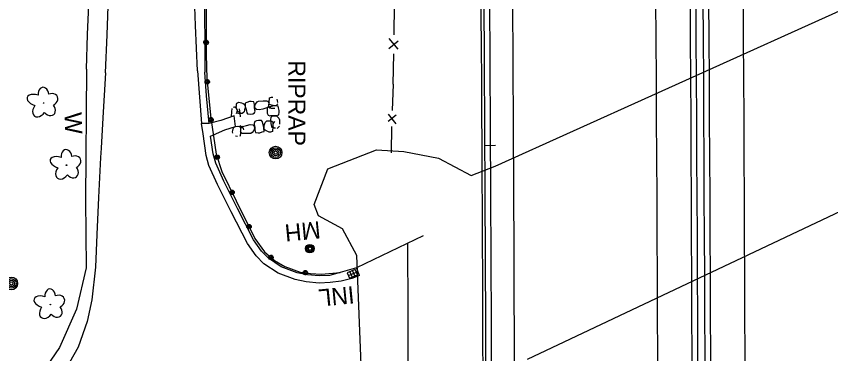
# Model space of a CAD drawing. Extents: x 588843 to 2552415, y 180129 to 269402.
# Drawn here: x 593781.7 to 594066, y 188272 to 188389.7 of the extents above; entities that cross this region are included whole.
import ezdxf

# ---------------------------------------------------------------- set-up
doc = ezdxf.new("R2010")
doc.units = 0
for name, color, linetype in [('Default', 7, 'Continuous'), ('E_AREA', 7, 'Continuous'), ('E_BMGRD_P', 7, 'Continuous'), ('E_DRN', 7, 'Continuous'), ('E_DRN_RipRap', 7, 'Continuous'), ('E_DRN_RipRap_Text', 7, 'Continuous'), ('E_DRN_Text', 7, 'Continuous'), ('E_FEN_P', 7, 'Continuous'), ('E_LAND_Vegetation', 7, 'Continuous'), ('E_MISCPROP', 7, 'Continuous'), ('E_RDWY', 7, 'Continuous'), ('E_RDWY_C_and_G', 7, 'Continuous'), ('E_RDWY_Gravel', 7, 'Continuous'), ('E_SGN', 7, 'Continuous'), ('E_UTL_MH', 7, 'Continuous'), ('E_UTL_MH_Text', 7, 'Continuous'), ('E_WAL', 7, 'Continuous'), ('E_WAL_Text', 7, 'Continuous'), ('P_RDWY_BarrierConc', 7, 'Continuous'), ('P_RDWY_C_and_G', 7, 'Continuous'), ('P_RDWY_C_and_GBack', 7, 'Continuous'), ('P_RDWY_C_and_GFace', 7, 'Continuous'), ('P_RDWY_PavtEdge', 7, 'Continuous')]:
    doc.layers.add(name, color=color, linetype=linetype)

# ---------------------------------------------------------------- blocks, each defined once
blk = doc.blocks.new('POLE')
at = {"layer": 'Default'}
for radius in [4.46, 3.35, 2.23, 1.12]:
    blk.add_circle((0, 0), radius, dxfattribs=at)
blk = doc.blocks.new('RIPRT')
at = {"layer": 'E_DRN_RipRap_Text'}
blk.add_text('RIPRAP', height=12, dxfattribs=at).set_placement((-0.14, -3.59))
blk = doc.blocks.new('INLO')
at = {"layer": 'E_DRN'}
for p, q in [((2, -4), (2, 0)), ((4, -4), (4, 0)), ((6, -2), (0, -2))]:
    blk.add_line(p, q, dxfattribs=at)
blk.add_lwpolyline([(0, -4), (6, -4), (6, 0), (0, 0), (0, -4)], close=True, dxfattribs=at)
blk = doc.blocks.new('INLT_37')
at = {"layer": 'E_DRN_Text'}
blk.add_text('INL', height=12, dxfattribs=at).set_placement((-11.03, -6))
blk = doc.blocks.new('MHO')
at = {"layer": 'Default'}
for centre, radius in [((0.08, -0.12), 3), ((0.08, -0.12), 2.43), ((0.07, -0.15), 1.94), ((0.02, -0.16), 1.21)]:
    blk.add_circle(centre, radius, dxfattribs=at)
blk = doc.blocks.new('MHT')
at = {"layer": 'E_UTL_MH_Text'}
blk.add_text('MH', height=12, dxfattribs=at).set_placement((-9.81, -6))
blk = doc.blocks.new('DTRE')
at = {"layer": 'Default'}
blk.add_circle((-0.18, 0), 0.183, dxfattribs=at)
for centre, major_axis, ratio in [((-1.87, 5.32), (1.36, -4.98), 0.782863), ((4.06, 2.74), (-5.27, -2.93), 0.691916), ((-5.87, 0.15), (4.93, -0.12), 0.832022), ((-2.49, -5.24), (1.8, 4.86), 0.716896), ((3.54, -3.71), (-5.01, 4.58), 0.560249)]:
    blk.add_ellipse(centre, major_axis=major_axis, ratio=ratio, start_param=1.570796, end_param=4.712389, dxfattribs=at)
blk = doc.blocks.new('W_26')
at = {"layer": 'E_WAL_Text'}
blk.add_text('W', height=12, dxfattribs=at).set_placement((-4.46, -6))

msp = doc.modelspace()

# ---------------------------------------------------------------- linework, layer by layer
at = {"layer": 'E_AREA'}
for points in [[(593902.79, 188250.54), (593900.56, 188306.25), (593895.49, 188315.57), (593887.11, 188320.1), (593885.68, 188323.97), (593890.4, 188336.47), (593907.43, 188343.11), (593916.95, 188342.51), (593929.09, 188340.24), (593940.49, 188334.14), (593948.81, 188337.39), (594085.58, 188399.16)], [(594080.03, 188326.7), (593960.02, 188269.93)]]:
    msp.add_lwpolyline(points, dxfattribs=at)
at = {"layer": 'E_BMGRD_P'}
for points in [[(593861.83, 188614.96), (593858.45, 188567.52), (593852.51, 188499.89), (593850.25, 188462.79), (593848.24, 188422.71), (593847.93, 188392.95), (593847.94, 188376.23), (593848.22, 188367.94)], [(593848.22, 188367.94), (593849.53, 188354.1), (593851.43, 188341.57), (593853.46, 188335.53), (593858.44, 188325.26), (593864.96, 188312.17), (593868.35, 188307.56), (593871.75, 188304.54), (593875.38, 188302.45), (593880.75, 188300.47), (593884.37, 188300), (593888.21, 188299.76), (593894.75, 188300.27)]]:
    msp.add_lwpolyline(points, dxfattribs=at)
for centre, radius in [((593851.79, 188340.51), 0.776), ((593851.79, 188340.51), 0.391), ((593856.99, 188328.26), 0.776), ((593856.99, 188328.26), 0.391), ((593862.9, 188316.32), 0.776), ((593862.9, 188316.32), 0.391)]:
    msp.add_circle(centre, radius, dxfattribs=at)
for centre, major_axis, ratio in [((593847.94, 188380.54), (0.259, 0.758), 0.999873), ((593847.94, 188380.54), (0.13, 0.382), 0.999873), ((593848.32, 188366.84), (0.774, 0.061), 0.998241), ((593848.32, 188366.84), (0.39, 0.031), 0.998241), ((593849.61, 188353.6), (0.767, 0.123), 0.996546), ((593849.61, 188353.6), (0.386, 0.062), 0.996546), ((593870.57, 188305.58), (-0.58, 0.516), 0.999998), ((593870.58, 188305.58), (-0.292, 0.26), 0.999998), ((593882.58, 188300.23), (-0.77, 0.1), 0.999994), ((593882.58, 188300.23), (-0.388, 0.05), 0.999994)]:
    msp.add_ellipse(centre, major_axis=major_axis, ratio=ratio, dxfattribs=at)
at = {"layer": 'E_DRN_RipRap'}
for p, q in [((593870.07, 188361.19), (593870.71, 188361.45)), ((593870.71, 188361.45), (593871.19, 188361.41)), ((593858.48, 188358.2), (593858.58, 188359.04)), ((593858.58, 188359.04), (593858.65, 188359.42)), ((593858.65, 188359.42), (593859.29, 188359.67)), ((593859.29, 188359.67), (593859.76, 188359.64)), ((593859.76, 188359.64), (593860.28, 188359.51)), ((593860.28, 188359.51), (593860.84, 188359.25)), ((593860.84, 188359.25), (593861.22, 188358.99)), ((593861.22, 188358.99), (593861.37, 188358.88)), ((593861.37, 188358.88), (593861.55, 188358.36)), ((593862.19, 188359.6), (593861.57, 188359.42)), ((593861.57, 188359.42), (593861.59, 188358.15)), ((593863.11, 188359.9), (593862.19, 188359.6)), ((593863.66, 188359.9), (593863.11, 188359.9)), ((593864.58, 188359.83), (593863.66, 188359.9)), ((593864.8, 188358.91), (593864.58, 188359.83)), ((593864.85, 188357.94), (593864.8, 188358.91)), ((593864.96, 188358.41), (593865.12, 188359.07)), ((593865.12, 188359.07), (593865.7, 188359.82)), ((593865.7, 188359.82), (593866.26, 188360.09)), ((593866.26, 188360.09), (593867.81, 188360.18)), ((593867.81, 188360.18), (593868.99, 188360.15)), ((593868.99, 188360.15), (593869.39, 188360.08)), ((593869.39, 188360.08), (593869.89, 188359.39)), ((593869.57, 188358.07), (593869.85, 188358.61)), ((593869.84, 188358.37), (593869.9, 188359.97)), ((593869.85, 188358.61), (593869.89, 188359.39)), ((593869.9, 188359.97), (593870, 188360.81)), ((593870, 188360.81), (593870.07, 188361.19)), ((593870.74, 188358.7), (593870.07, 188358.89)), ((593871.35, 188358.53), (593870.74, 188358.7)), ((593872.01, 188358.44), (593871.35, 188358.53)), ((593872.54, 188358.6), (593872.01, 188358.44)), ((593872.65, 188358.74), (593872.54, 188358.6)), ((593872.62, 188360.78), (593872.76, 188360.26)), ((593872.92, 188359.11), (593872.65, 188358.74)), ((593872.76, 188360.26), (593872.81, 188359.64)), ((593856.8, 188354.77), (593856.86, 188356.34)), ((593856.86, 188356.34), (593857, 188357.51)), ((593857.44, 188357.98), (593857.83, 188358.08)), ((593857.83, 188358.08), (593858.56, 188357.66)), ((593858.93, 188356.71), (593858.34, 188358.2)), ((593858.84, 188356.94), (593858.56, 188357.66)), ((593858.57, 188355.81), (593858.82, 188356.32)), ((593859.26, 188355.72), (593858.76, 188355.88)), ((593858.82, 188356.32), (593858.84, 188356.94)), ((593859.22, 188356.31), (593858.93, 188356.71)), ((593859.53, 188356.2), (593859.22, 188356.31)), ((593859.99, 188355.73), (593859.26, 188355.72)), ((593859.41, 188357.37), (593859.7, 188355.93)), ((593859.7, 188355.93), (593859.8, 188354.6)), ((593860.53, 188355.79), (593859.99, 188355.73)), ((593860.98, 188356.07), (593860.53, 188355.79)), ((593861.22, 188356.37), (593860.98, 188356.07)), ((593861.37, 188357.06), (593861.22, 188356.37)), ((593861.5, 188357.69), (593861.37, 188357.06)), ((593861.55, 188358.36), (593861.5, 188357.69)), ((593861.59, 188358.15), (593861.77, 188357.49)), ((593861.77, 188357.49), (593861.98, 188356.65)), ((593861.98, 188356.65), (593862.13, 188356.03)), ((593862.13, 188356.03), (593862.42, 188355.66)), ((593862.42, 188355.66), (593862.56, 188355.6)), ((593862.56, 188355.6), (593863.5, 188355.58)), ((593863.5, 188355.58), (593864.24, 188355.67)), ((593864.24, 188355.67), (593864.85, 188356.01)), ((593864.98, 188356.96), (593864.85, 188357.94)), ((593864.85, 188356.01), (593865.07, 188356.6)), ((593865.04, 188357.55), (593864.96, 188358.41)), ((593865.07, 188356.6), (593864.98, 188356.96)), ((593865.5, 188357.14), (593865.04, 188357.55)), ((593866.45, 188357.05), (593865.5, 188357.14)), ((593867.74, 188357.28), (593866.45, 188357.05)), ((593869.14, 188357.71), (593867.74, 188357.28)), ((593869.14, 188357.71), (593869.57, 188358.07)), ((593869.25, 188357.57), (593869.2, 188356.62)), ((593869.2, 188356.62), (593869.25, 188355.86)), ((593869.32, 188357.71), (593869.25, 188357.57)), ((593869.25, 188355.86), (593869.55, 188355.23)), ((593869.7, 188357.99), (593869.32, 188357.71)), ((593870.11, 188358.03), (593869.64, 188358.3)), ((593870.31, 188358.1), (593869.7, 188357.99)), ((593869.94, 188357.88), (593869.84, 188358.37)), ((593870.19, 188357.66), (593869.94, 188357.88)), ((593870.49, 188357.96), (593870.11, 188358.03)), ((593870.68, 188357.5), (593870.19, 188357.66)), ((593871.15, 188358.27), (593870.31, 188358.1)), ((593871.41, 188357.5), (593870.68, 188357.5)), ((593871.81, 188358.42), (593871.15, 188358.27)), ((593871.95, 188357.56), (593871.41, 188357.5)), ((593873.05, 188358.36), (593871.81, 188358.42)), ((593873.2, 188357.72), (593873.05, 188358.36)), ((593873.46, 188356.77), (593873.2, 188357.72)), ((593873.33, 188355.29), (593873.44, 188356.22)), ((593873.44, 188356.22), (593873.46, 188356.77)), ((593864.88, 188352.92), (593864.66, 188352.33)), ((593865.47, 188353.26), (593864.88, 188352.92)), ((593866.21, 188353.35), (593865.47, 188353.26)), ((593867.14, 188353.34), (593866.21, 188353.35)), ((593867.28, 188353.28), (593867.14, 188353.34)), ((593867.58, 188352.91), (593867.28, 188353.28)), ((593867.73, 188352.3), (593867.58, 188352.91)), ((593868.49, 188352.57), (593868.72, 188352.88)), ((593868.72, 188352.88), (593869.17, 188353.16)), ((593869.17, 188353.16), (593869.7, 188353.22)), ((593869.55, 188355.23), (593870.13, 188354.98)), ((593869.7, 188353.22), (593870.42, 188353.23)), ((593870.13, 188354.98), (593870.48, 188355.04)), ((593870.42, 188353.23), (593870.92, 188353.07)), ((593870.48, 188355.04), (593871.46, 188355.12)), ((593870.51, 188353.55), (593870.64, 188354.51)), ((593870.68, 188352.22), (593870.51, 188353.55)), ((593870.64, 188354.51), (593871.06, 188354.95)), ((593870.92, 188353.07), (593871.16, 188352.85)), ((593871.06, 188354.95), (593871.91, 188354.98)), ((593871.16, 188352.85), (593871.27, 188352.36)), ((593871.46, 188355.12), (593872.42, 188355.11)), ((593871.96, 188353.03), (593871.53, 188352.67)), ((593871.91, 188354.98), (593872.56, 188354.78)), ((593872.42, 188355.11), (593873.33, 188355.29)), ((593872.56, 188354.78), (593873.27, 188354.15)), ((593873.27, 188354.15), (593873.52, 188353.57)), ((593873.52, 188353.57), (593873.53, 188351.99)), ((593857.24, 188349.85), (593857.41, 188350.44)), ((593857.41, 188350.44), (593857.6, 188350.85)), ((593857.6, 188350.85), (593857.69, 188351.01)), ((593857.69, 188351.01), (593858.18, 188351.26)), ((593858.18, 188351.26), (593858.84, 188351.29)), ((593858.84, 188351.29), (593859.48, 188351.23)), ((593859.09, 188351.4), (593859.58, 188351.24)), ((593859.48, 188351.23), (593860.18, 188351.16)), ((593859.58, 188351.24), (593859.83, 188351.02)), ((593859.65, 188351.55), (593860.28, 188351.18)), ((593859.83, 188351.02), (593859.93, 188350.53)), ((593859.93, 188350.53), (593859.89, 188348.93)), ((593859.93, 188350.29), (593859.89, 188349.51)), ((593860.2, 188350.84), (593859.93, 188350.29)), ((593860.18, 188351.16), (593860.51, 188350.96)), ((593860.63, 188351.2), (593860.2, 188350.84)), ((593860.51, 188350.96), (593860.85, 188350.54)), ((593860.63, 188351.2), (593862.01, 188351.63)), ((593860.85, 188350.54), (593860.99, 188350.01)), ((593862.01, 188351.63), (593863.29, 188351.87)), ((593863.29, 188351.87), (593864.24, 188351.78)), ((593864.24, 188351.78), (593864.69, 188351.38)), ((593864.78, 188350.52), (593864.63, 188349.86)), ((593864.66, 188352.33), (593864.75, 188351.97)), ((593864.69, 188351.38), (593864.78, 188350.52)), ((593864.75, 188351.97), (593864.88, 188350.99)), ((593864.88, 188350.99), (593864.94, 188350.01)), ((593864.94, 188350.01), (593865.17, 188349.1)), ((593867.95, 188351.45), (593867.73, 188352.3)), ((593868.13, 188350.79), (593867.95, 188351.45)), ((593868.16, 188349.52), (593868.13, 188350.79)), ((593868.17, 188350.59), (593868.21, 188351.26)), ((593868.36, 188350.06), (593868.17, 188350.59)), ((593868.21, 188351.26), (593868.34, 188351.89)), ((593868.34, 188351.89), (593868.49, 188352.57)), ((593868.5, 188349.95), (593868.36, 188350.06)), ((593868.88, 188349.69), (593868.5, 188349.95)), ((593871.04, 188350.79), (593870.68, 188352.22)), ((593871.12, 188349.92), (593871.06, 188349.54)), ((593871.22, 188350.76), (593871.12, 188349.92)), ((593871.27, 188352.36), (593871.22, 188350.76)), ((593871.26, 188352.12), (593871.23, 188351.35)), ((593871.73, 188350.66), (593871.23, 188351.35)), ((593871.53, 188352.67), (593871.26, 188352.12)), ((593872.13, 188350.59), (593871.73, 188350.66)), ((593873.55, 188351.32), (593872.67, 188350.54)), ((593857.19, 188349.32), (593857.24, 188349.85)), ((593857.23, 188348.85), (593857.19, 188349.32)), ((593858.92, 188347.71), (593858.23, 188347.83)), ((593859.79, 188348.09), (593859.72, 188347.71)), ((593859.89, 188348.93), (593859.79, 188348.09)), ((593860.4, 188348.83), (593859.89, 188349.51)), ((593860.79, 188348.76), (593860.4, 188348.83)), ((593861.96, 188348.74), (593860.79, 188348.76)), ((593863.5, 188348.83), (593861.96, 188348.74)), ((593864.05, 188349.1), (593863.5, 188348.83)), ((593864.63, 188349.86), (593864.05, 188349.1)), ((593865.17, 188349.1), (593866.09, 188349.03)), ((593866.09, 188349.03), (593866.63, 188349.04)), ((593866.63, 188349.04), (593867.54, 188349.34)), ((593867.54, 188349.34), (593868.16, 188349.52)), ((593869.44, 188349.44), (593868.88, 188349.69)), ((593869.95, 188349.31), (593869.44, 188349.44)), ((593870.43, 188349.28), (593869.95, 188349.31)), ((593871.06, 188349.54), (593870.43, 188349.28))]:
    msp.add_line(p, q, dxfattribs=at)
at = {"layer": 'E_FEN_P'}
for p, q in [((593914.94, 188378.2), (593911.77, 188381.95)), ((593911.72, 188378.42), (593914.92, 188381.16)), ((593914.27, 188355.22), (593911.45, 188352.95)), ((593911.51, 188355.49), (593914.13, 188352.19))]:
    msp.add_line(p, q, dxfattribs=at)
for points in [[(593913.53, 188383.17), (593913.69, 188393.8)], [(593913.27, 188365.97), (593913.43, 188376.59)], [(593913.27, 188365.97), (593912.85, 188356.84)], [(593912.66, 188351.19), (593912.51, 188342.05)]]:
    msp.add_lwpolyline(points, dxfattribs=at)
at = {"layer": 'E_RDWY'}
msp.add_line((593848.94, 188352.22), (593846.37, 188352.22), dxfattribs=at)
for points in [[(593844.94, 188370.59), (593844.22, 188386.45), (593843.71, 188399.59)], [(593812.81, 188369.98), (593813.37, 188383.18), (593813.82, 188396.56)], [(593812.81, 188369.98), (593811.87, 188354.28), (593811.29, 188343.71), (593811.11, 188340.46), (593810.36, 188326.41), (593809.81, 188313.54), (593809.32, 188302.14), (593807.98, 188290.75), (593806.39, 188283.16), (593803.22, 188274.31), (593798.77, 188266.19), (593793.8, 188260.18), (593788.5, 188254.9), (593781.81, 188249.58), (593772.97, 188243.5)], [(593844.94, 188370.59), (593846.37, 188352.22)], [(593850.39, 188341.75), (593849.5, 188347.86), (593854.46, 188350.08), (593858.18, 188351.26), (593857.77, 188354.92), (593853.12, 188353.29), (593848.94, 188352.22)], [(593918.92, 188260.44), (593918.41, 188268.91), (593918.46, 188286.63), (593918.29, 188310.53)]]:
    msp.add_lwpolyline(points, dxfattribs=at)
at = {"layer": 'E_RDWY_C_and_G'}
msp.add_line((593901.45, 188299.3), (593900.41, 188301.94), dxfattribs=at)
for points in [[(593847.98, 188341.11), (593846.84, 188348.69), (593846.37, 188352.22)], [(593894.75, 188300.27), (593890.98, 188299.28), (593887.42, 188299.11), (593883.26, 188299.48), (593879.68, 188300.21), (593874.17, 188302.29), (593869.66, 188305.27), (593867.31, 188307.74), (593864.47, 188311.73), (593858.85, 188322.64), (593854.12, 188332.11), (593851.27, 188338.47), (593850.39, 188341.75)], [(593901.45, 188299.3), (593898.81, 188298.15), (593895.11, 188297.27), (593891.19, 188296.79), (593887.37, 188296.6), (593882.89, 188297), (593878.99, 188297.8), (593873.02, 188300.05), (593868.05, 188303.34), (593865.38, 188306.14), (593862.33, 188310.42), (593856.62, 188321.51), (593851.86, 188331.04), (593848.9, 188337.63), (593847.98, 188341.11)]]:
    msp.add_lwpolyline(points, dxfattribs=at)
at = {"layer": 'E_RDWY_Gravel'}
for points in [[(593856.86, 188620.02), (593855.07, 188583.71), (593852.08, 188537.24), (593850.02, 188499.2), (593848.61, 188462.07), (593847.54, 188423.48), (593847.38, 188394.52), (593847.45, 188376.15), (593847.46, 188370.15)], [(593806.21, 188371.19), (593805.8, 188325.67), (593806.09, 188301.88), (593802.63, 188287.53), (593796.7, 188274.16), (593790.91, 188265.64), (593783.7, 188258.17), (593776.29, 188252.01), (593758.44, 188240.45), (593728.62, 188221.72), (593720.11, 188216.47), (593691.17, 188203.12), (593680.23, 188197.49)], [(593848.94, 188352.22), (593848.05, 188361.98), (593847.46, 188370.15)]]:
    msp.add_lwpolyline(points, dxfattribs=at)
at = {"layer": 'E_SGN'}
msp.add_lwpolyline([(593945, 188344.65), (593948.94, 188344.69)], dxfattribs=at)
at = {"layer": 'E_WAL'}
for points in [[(593806.21, 188371.19), (593806.47, 188383.35), (593807.07, 188396.39), (593807.79, 188410.59), (593808.75, 188427.79), (593809.61, 188443.07), (593810.66, 188460.58), (593811.96, 188479.31), (593812.65, 188494.43), (593813.39, 188499.93)], [(593923.65, 188313.11), (593900.41, 188301.94), (593894.75, 188300.27)]]:
    msp.add_lwpolyline(points, dxfattribs=at)
at = {"layer": 'P_RDWY_BarrierConc'}
for radius in [57298.53, 57300.53, 57303.03, 57305.03]:
    msp.add_arc((536719.48, 188049.55), radius, 359.769059, 0.6479963, dxfattribs=at)
at = {"layer": 'P_RDWY_C_and_G'}
msp.add_arc((536719.48, 188049.55), 57228.53, 359.920406, 0.647996, dxfattribs=at)
at = {"layer": 'P_RDWY_C_and_GBack'}
msp.add_arc((536719.48, 188049.55), 57225.53, 359.920487, 0.647996, dxfattribs=at)
at = {"layer": 'P_RDWY_C_and_GFace'}
msp.add_arc((536719.48, 188049.55), 57226.53, 359.920487, 0.647996, dxfattribs=at)
at = {"layer": 'P_RDWY_PavtEdge'}
for radius, start, end in [(57236.53, 359.944955, 0.647996), (57286.53, 359.769059, 0.647996), (57317.03, 359.769059, 0.6479963)]:
    msp.add_arc((536719.48, 188049.55), radius, start, end, dxfattribs=at)

# ---------------------------------------------------------------- block references
at = {"layer": 'E_DRN', "xscale": 0.5, "yscale": 0.5, "rotation": -158.13633222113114}
msp.add_blockref('INLO', (593900.75, 188299.44), dxfattribs=at)
at = {"layer": 'E_DRN_RipRap_Text', "xscale": 0.5, "yscale": 0.5, "rotation": -90.08889475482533}
msp.add_blockref('RIPRT', (593878.41, 188374.25), dxfattribs=at)
at = {"layer": 'E_DRN_Text', "xscale": 0.49999999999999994, "yscale": 0.5, "rotation": -174.38738650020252}
msp.add_blockref('INLT_37', (593894.14, 188292.03), dxfattribs=at)
at = {"layer": 'E_LAND_Vegetation', "xscale": 0.5, "yscale": 0.5, "rotation": -155.21508863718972}
for p in [(593791.09, 188359.41), (593799.11, 188337.7), (593793.47, 188289.08)]:
    msp.add_blockref('DTRE', p, dxfattribs=at)
at = {"layer": 'E_MISCPROP'}
for p, xscale, yscale, rotation in [((593872.18, 188342.13), 0.5, 0.5, -90.08889475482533), ((593779.91, 188296.48), 0.49999999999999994, 0.49999999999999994, -154.79394034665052)]:
    msp.add_blockref('POLE', p, dxfattribs=dict(at, xscale=xscale, yscale=yscale, rotation=rotation))
at = {"layer": 'E_UTL_MH', "xscale": 0.49999999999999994, "yscale": 0.5, "rotation": -174.38738650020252}
msp.add_blockref('MHO', (593884.19, 188308.56), dxfattribs=at)
at = {"layer": 'E_UTL_MH_Text', "xscale": 0.49999999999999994, "yscale": 0.5, "rotation": -174.38738650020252}
msp.add_blockref('MHT', (593882.96, 188314.76), dxfattribs=at)
at = {"layer": 'E_WAL_Text', "xscale": 0.5, "yscale": 0.49999999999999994, "rotation": -87.3533390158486}
msp.add_blockref('W_26', (593801.53, 188353.92), dxfattribs=at)

doc.saveas('drawing.dxf')
